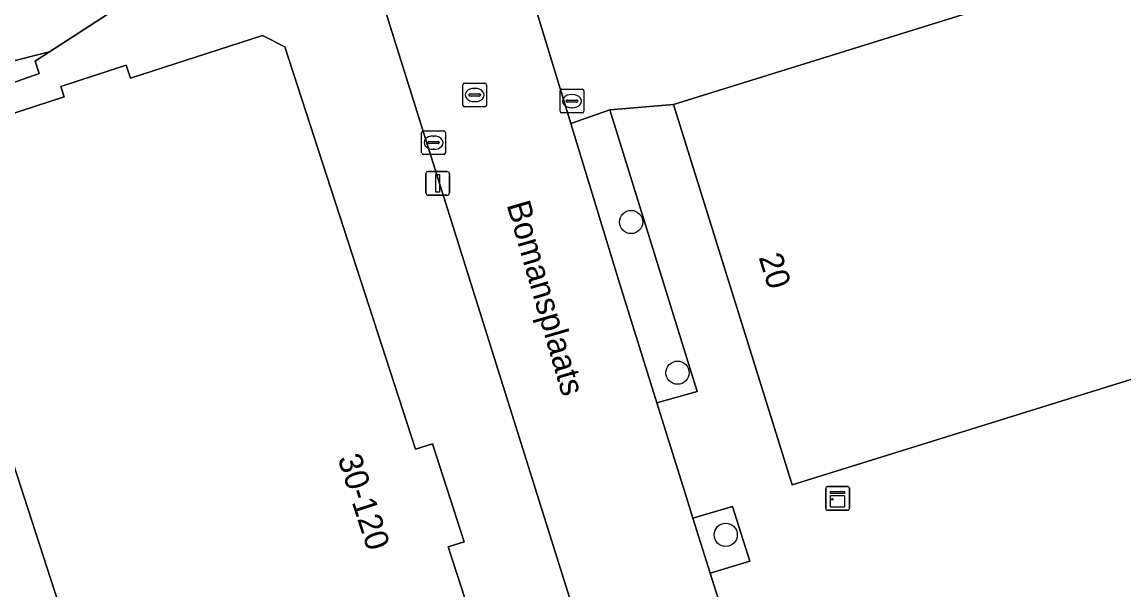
# Model space of a CAD drawing. Extents: x 161347 to 161881, y 382161 to 382804.
# Drawn here: x 161713.79 to 161760.21, y 382447.38 to 382471.33 of the extents above; entities that cross this region are included whole.
import ezdxf

# ---------------------------------------------------------------- set-up
doc = ezdxf.new("R2010")
doc.units = 0
for name, color, linetype in [('IMGEO_Boom', 7, 'Continuous'), ('IMGEO_Groenvoorziening', 7, 'Continuous'), ('IMGEO_Kast', 7, 'Continuous'), ('IMGEO_Kolk', 7, 'Continuous'), ('IMGEO_Lichtmast', 7, 'Continuous'), ('IMGEO_Openbare_ruimte_label', 7, 'Continuous'), ('IMGEO_Pand', 7, 'Continuous'), ('IMGEO_Pand_nummerreeks', 7, 'Continuous'), ('IMGEO_Rijbaan_lokaal_open', 7, 'Continuous'), ('IMGEO_Rioolput', 7, 'Continuous'), ('IMGEO_Voetpad_open', 7, 'Continuous')]:
    doc.layers.add(name, color=color, linetype=linetype)

msp = doc.modelspace()

# ---------------------------------------------------------------- linework, layer by layer
at = {"layer": 'IMGEO_Boom'}
for centre in [(161739.449, 382462.895), (161741.405, 382456.543), (161743.435, 382449.708)]:
    msp.add_circle(centre, 0.489, dxfattribs=at)
at = {"layer": 'IMGEO_Groenvoorziening'}
for points in [[(161723.237, 382475.454), (161722.614, 382477.411), (161718.908, 382479.002), (161713.011, 382475.39), (161710.549, 382473.96), (161709.541, 382473.374), (161708.224, 382471.041), (161709.207, 382469.376), (161711.307, 382469.157), (161714.949, 382470.071)], [(161738.546, 382467.628), (161736.911, 382467.053), (161738.977, 382460.274), (161740.535, 382455.275), (161742.236, 382455.745)], [(161743.72, 382450.897), (161742.055, 382450.408), (161742.785, 382448.094), (161744.454, 382448.592)]]:
    msp.add_lwpolyline(points, close=True, dxfattribs=at)
at = {"layer": 'IMGEO_Kast'}
for p, q in [((161747.647, 382450.819), (161747.647, 382451.66)), ((161747.647, 382451.66), (161747.647, 382450.819)), ((161747.722, 382451.744), (161748.563, 382451.744)), ((161748.563, 382451.744), (161747.722, 382451.744)), ((161748.647, 382451.669), (161748.647, 382450.828)), ((161748.647, 382450.828), (161748.647, 382451.669)), ((161748.572, 382450.744), (161747.731, 382450.744)), ((161747.731, 382450.744), (161748.572, 382450.744))]:
    msp.add_line(p, q, dxfattribs=at)
for points in [[(161747.842, 382451.534), (161748.442, 382451.534), (161748.442, 382451.449), (161747.842, 382451.449), (161747.842, 382451.534)], [(161747.842, 382451.359), (161748.442, 382451.359), (161748.442, 382450.87), (161747.842, 382450.87), (161747.842, 382451.359)]]:
    msp.add_lwpolyline(points, dxfattribs=at)
msp.add_circle((161747.926, 382451.208), 0.0377, dxfattribs=at)
for centre, start, end in [((161747.725, 382451.666), 92.4484, 184.2845), ((161747.725, 382451.666), 92.4484, 184.2845), ((161748.569, 382451.666), 2.4484, 94.2845), ((161748.569, 382451.666), 2.4484, 94.2845), ((161747.725, 382450.822), 182.4484, 274.2845), ((161747.725, 382450.822), 182.4484, 274.2845), ((161748.569, 382450.822), 272.4484, 4.2845), ((161748.569, 382450.822), 272.4484, 4.2845)]:
    msp.add_arc(centre, 0.0779, start, end, dxfattribs=at)
at = {"layer": 'IMGEO_Kolk'}
for p, q in [((161736.458, 382467.567), (161736.458, 382468.419)), ((161736.533, 382468.493), (161737.385, 382468.493)), ((161736.946, 382468.273), (161736.971, 382468.273)), ((161737.459, 382468.419), (161737.459, 382467.567)), ((161736.717, 382467.987), (161736.717, 382467.999)), ((161737.155, 382467.95), (161736.757, 382467.95)), ((161736.76, 382468.036), (161737.158, 382468.036)), ((161737.201, 382467.999), (161737.201, 382467.987)), ((161737.385, 382467.493), (161736.533, 382467.493)), ((161736.969, 382467.713), (161736.944, 382467.713)), ((161730.626, 382465.815), (161730.626, 382466.667)), ((161730.701, 382466.741), (161731.553, 382466.741)), ((161731.114, 382466.521), (161731.139, 382466.521)), ((161731.627, 382466.667), (161731.627, 382465.815)), ((161730.885, 382466.235), (161730.885, 382466.247)), ((161731.323, 382466.198), (161730.925, 382466.198)), ((161730.928, 382466.284), (161731.326, 382466.284)), ((161731.137, 382465.961), (161731.112, 382465.961)), ((161731.369, 382466.247), (161731.369, 382466.235)), ((161731.553, 382465.741), (161730.701, 382465.741))]:
    msp.add_line(p, q, dxfattribs=at)
for points in [[(161736.458, 382467.567), (161736.458, 382468.419)], [(161736.533, 382468.493), (161737.385, 382468.493)], [(161737.459, 382468.419), (161737.459, 382467.567)], [(161737.385, 382467.493), (161736.533, 382467.493)], [(161730.626, 382465.815), (161730.626, 382466.667)], [(161730.701, 382466.741), (161731.553, 382466.741)], [(161731.627, 382466.667), (161731.627, 382465.815)], [(161731.553, 382465.741), (161730.701, 382465.741)]]:
    msp.add_lwpolyline(points, dxfattribs=at)
for centre, radius, start, end in [((161736.535, 382468.417), 0.0765, 91.552, 178.448), ((161736.535, 382468.417), 0.0765, 91.552, 178.448), ((161737.383, 382468.417), 0.0765, 1.552, 88.448), ((161737.383, 382468.417), 0.0765, 1.552, 88.448), ((161736.757, 382467.996), 0.0403, 85.8775, 175.7526), ((161736.754, 382467.986), 0.0366, 178.938, 274.7102), ((161737.158, 382467.993), 0.043, 264.8664, 352.4533), ((161737.162, 382467.998), 0.0386, 1.7309, 96.639), ((161736.535, 382467.569), 0.0765, 181.552, 268.448), ((161736.535, 382467.569), 0.0765, 181.552, 268.448), ((161737.383, 382467.569), 0.0765, 271.552, 358.448), ((161737.383, 382467.569), 0.0765, 271.552, 358.448), ((161730.703, 382466.665), 0.0765, 91.552, 178.448), ((161730.703, 382466.665), 0.0765, 91.552, 178.448), ((161731.551, 382466.665), 0.0765, 1.552, 88.448), ((161731.551, 382466.665), 0.0765, 1.552, 88.448), ((161730.925, 382466.244), 0.0403, 85.8775, 175.7526), ((161730.922, 382466.234), 0.0366, 178.938, 274.7102), ((161731.326, 382466.241), 0.043, 264.8664, 352.4533), ((161731.33, 382466.246), 0.0386, 1.7309, 96.639), ((161730.703, 382465.817), 0.0765, 181.552, 268.448), ((161730.703, 382465.817), 0.0765, 181.552, 268.448), ((161731.551, 382465.817), 0.0765, 271.552, 358.448), ((161731.551, 382465.817), 0.0765, 271.552, 358.448)]:
    msp.add_arc(centre, radius, start, end, dxfattribs=at)
for centre, major_axis, ratio, start_param, end_param in [((161736.945, 382467.993), (-0.387, 0.002), 0.722429, 4.712389, 7.853982), ((161736.97, 382467.993), (-0.39, 0.002), 0.717154, 1.570796, 4.712389), ((161731.113, 382466.241), (-0.387, 0.002), 0.722429, 4.712389, 7.853982), ((161731.138, 382466.241), (-0.39, 0.002), 0.717154, 1.570796, 4.712389)]:
    msp.add_ellipse(centre, major_axis=major_axis, ratio=ratio, start_param=start_param, end_param=end_param, dxfattribs=at)
at = {"layer": 'IMGEO_Lichtmast'}
for p, q in [((161730.903, 382465.024), (161731.693, 382465.024)), ((161731.693, 382465.024), (161730.903, 382465.024)), ((161730.803, 382464.124), (161730.803, 382464.924)), ((161730.803, 382464.924), (161730.803, 382464.124)), ((161731.793, 382464.924), (161731.793, 382464.124)), ((161731.793, 382464.124), (161731.793, 382464.924)), ((161731.693, 382464.024), (161730.903, 382464.024)), ((161730.903, 382464.024), (161731.693, 382464.024))]:
    msp.add_line(p, q, dxfattribs=at)
msp.add_lwpolyline([(161731.223, 382464.899), (161731.373, 382464.899), (161731.373, 382464.149), (161731.223, 382464.149), (161731.223, 382464.899)], dxfattribs=at)
for centre, start, end in [((161730.903, 382464.924), 90, 180), ((161730.903, 382464.924), 90, 180), ((161731.693, 382464.924), 0, 90), ((161731.693, 382464.924), 360, 90), ((161730.903, 382464.124), 180, 270), ((161730.903, 382464.124), 180, 270), ((161731.693, 382464.124), 270, 0), ((161731.693, 382464.124), 270, 0)]:
    msp.add_arc(centre, 0.1, start, end, dxfattribs=at)
at = {"layer": 'IMGEO_Pand'}
msp.add_lwpolyline([(161766.816, 382475.812), (161741.239, 382467.848), (161746.233, 382451.809), (161780.635, 382462.52), (161781.784, 382462.878), (161783.757, 382463.493), (161785.018, 382459.445), (161783.044, 382458.83), (161783.538, 382457.245), (161797.754, 382411.585), (161804.518, 382415.294), (161807.53, 382405.622), (161800.311, 382403.374), (161812.615, 382363.855)], dxfattribs=at)
msp.add_lwpolyline([(161737.439, 382431.641), (161731.746, 382449.2), (161732.418, 382449.418), (161731.079, 382453.547), (161730.364, 382453.315), (161724.862, 382470.285), (161723.923, 382470.764), (161718.358, 382468.959), (161718.182, 382469.502), (161715.427, 382468.608), (161715.568, 382468.172), (161709.907, 382466.336), (161709.35, 382465.246), (161710.691, 382461.109), (161721.695, 382427.173), (161722.435, 382426.796), (161728.069, 382428.623), (161728.225, 382428.143), (161730.895, 382429.009), (161730.745, 382429.471)], close=True, dxfattribs=at)
at = {"layer": 'IMGEO_Rijbaan_lokaal_open'}
for points in [[(161727.934, 382475.503), (161740.031, 382436.95)], [(161738.977, 382460.274), (161736.911, 382467.053), (161734.468, 382475.066)], [(161745.334, 382440.013), (161742.785, 382448.094), (161742.055, 382450.408), (161741.778, 382451.285), (161740.535, 382455.275), (161738.977, 382460.274)]]:
    msp.add_lwpolyline(points, dxfattribs=at)
at = {"layer": 'IMGEO_Rioolput'}
for p, q in [((161732.434, 382468.75), (161733.286, 382468.75)), ((161732.359, 382467.824), (161732.359, 382468.676)), ((161732.661, 382468.293), (161733.059, 382468.293)), ((161732.847, 382468.53), (161732.872, 382468.53)), ((161733.36, 382468.676), (161733.36, 382467.824)), ((161732.618, 382468.244), (161732.618, 382468.256)), ((161733.056, 382468.207), (161732.658, 382468.207)), ((161732.87, 382467.97), (161732.845, 382467.97)), ((161733.102, 382468.256), (161733.102, 382468.244)), ((161733.286, 382467.75), (161732.434, 382467.75))]:
    msp.add_line(p, q, dxfattribs=at)
for points in [[(161732.434, 382468.75), (161733.286, 382468.75)], [(161732.359, 382467.824), (161732.359, 382468.676)], [(161733.36, 382468.676), (161733.36, 382467.824)], [(161733.286, 382467.75), (161732.434, 382467.75)]]:
    msp.add_lwpolyline(points, dxfattribs=at)
for centre, radius, start, end in [((161732.436, 382468.674), 0.0765, 91.552, 178.448), ((161732.436, 382468.674), 0.0765, 91.552, 178.448), ((161733.284, 382468.674), 0.0765, 1.552, 88.448), ((161733.284, 382468.674), 0.0765, 1.552, 88.448), ((161732.658, 382468.253), 0.0403, 85.8775, 175.7526), ((161733.063, 382468.255), 0.0386, 1.7309, 96.639), ((161732.436, 382467.826), 0.0765, 181.552, 268.448), ((161732.436, 382467.826), 0.0765, 181.552, 268.448), ((161732.655, 382468.243), 0.0366, 178.938, 274.7102), ((161733.059, 382468.25), 0.043, 264.8664, 352.4533), ((161733.284, 382467.826), 0.0765, 271.552, 358.448), ((161733.284, 382467.826), 0.0765, 271.552, 358.448)]:
    msp.add_arc(centre, radius, start, end, dxfattribs=at)
for centre, major_axis, ratio, start_param, end_param in [((161732.846, 382468.25), (-0.387, 0.002), 0.722429, 4.712389, 7.853982), ((161732.871, 382468.25), (-0.39, 0.002), 0.717154, 1.570796, 4.712389)]:
    msp.add_ellipse(centre, major_axis=major_axis, ratio=ratio, start_param=start_param, end_param=end_param, dxfattribs=at)
at = {"layer": 'IMGEO_Voetpad_open'}
for points in [[(161734.644, 382478.978), (161734.865, 382478.218), (161735.005, 382477.734), (161734.468, 382475.066), (161736.911, 382467.053), (161738.546, 382467.628), (161741.239, 382467.848), (161766.816, 382475.812), (161767.193, 382474.599), (161779.657, 382478.48), (161779.28, 382479.692), (161776.845, 382478.934), (161776.421, 382480.3), (161778.854, 382481.057), (161778.389, 382482.55)], [(161727.934, 382475.503), (161722.614, 382477.411), (161723.237, 382475.454), (161714.949, 382470.071), (161714.345, 382469.679), (161714.515, 382469.156), (161708.743, 382467.121)], [(161740.031, 382436.95), (161727.934, 382475.503)], [(161709.907, 382466.336), (161715.568, 382468.172), (161715.427, 382468.608), (161718.182, 382469.502), (161718.358, 382468.959), (161723.923, 382470.764), (161724.862, 382470.285), (161730.364, 382453.315), (161731.079, 382453.547), (161732.418, 382449.418), (161731.746, 382449.2), (161737.439, 382431.641), (161730.745, 382429.471), (161730.895, 382429.009), (161738.206, 382431.323)], [(161783.538, 382457.245), (161783.044, 382458.83), (161781.784, 382462.878), (161780.635, 382462.52), (161746.233, 382451.809), (161741.239, 382467.848), (161738.546, 382467.628), (161742.236, 382455.745), (161740.535, 382455.275), (161741.778, 382451.285), (161742.055, 382450.408), (161743.72, 382450.897), (161744.454, 382448.592), (161742.785, 382448.094), (161745.334, 382440.013)]]:
    msp.add_lwpolyline(points, dxfattribs=at)
for points in [[(161714.515, 382469.156), (161714.345, 382469.679), (161714.949, 382470.071), (161711.307, 382469.157), (161709.207, 382469.376), (161708.224, 382471.041), (161704.876, 382469.993), (161706.646, 382465.174), (161707.851, 382465.285), (161708.743, 382467.121)], [(161709.351, 382460.673), (161706.096, 382459.614), (161706.269, 382459.061), (161711.019, 382443.834), (161716.843, 382425.223), (161712.68, 382423.888), (161712.889, 382423.225), (161721.908, 382426.143), (161728.225, 382428.143), (161728.069, 382428.623), (161722.435, 382426.796), (161721.695, 382427.173), (161710.691, 382461.109)]]:
    msp.add_lwpolyline(points, close=True, dxfattribs=at)

# ---------------------------------------------------------------- texts
at = {"layer": 'IMGEO_Openbare_ruimte_label'}
msp.add_text('Bomansplaats', height=1, rotation=286.2052, dxfattribs=at).set_placement((161734.198, 382463.628))
at = {"layer": 'IMGEO_Pand_nummerreeks'}
for s, rotation, p in [('20', 287.2948, (161744.814, 382461.413)), ('30-120', 287.95, (161727.079, 382452.937))]:
    msp.add_text(s, height=1, rotation=rotation, dxfattribs=at).set_placement(p)

doc.saveas('drawing.dxf')
